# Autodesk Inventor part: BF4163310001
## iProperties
Shininess: 64.0
Angle Display Precision: 2
Document Length Units: 11272
Document Angle Units: 11279
Document Time Units: 11290
Document Mass Units: 11286
Document Length Units Precision: 3
Document Angle Units Precision: 2
Created: 2002-08
Part Number: BF4163310001
Material: Bronze, Soft Tin
Description: PLUG, PIPE, RED BRASS, 1/8" NPT, 125#
Vendor: BF4163310001
Document SubType Name: Modeling
Designer: TIM
Density: 8.874
Volumn: 3.648847453226989
Area: 14.273739184722222
PropertySet Name: Model Information
Control State: 0
Master: False
Checked Out: False
Title: PLUG, PIPE, RED BRASS, 1/8" NPT, 125#
Author: TIM
Revision Number: 0
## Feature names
1. Extrusion1
2. TaperEdge1
3. Extrusion2
